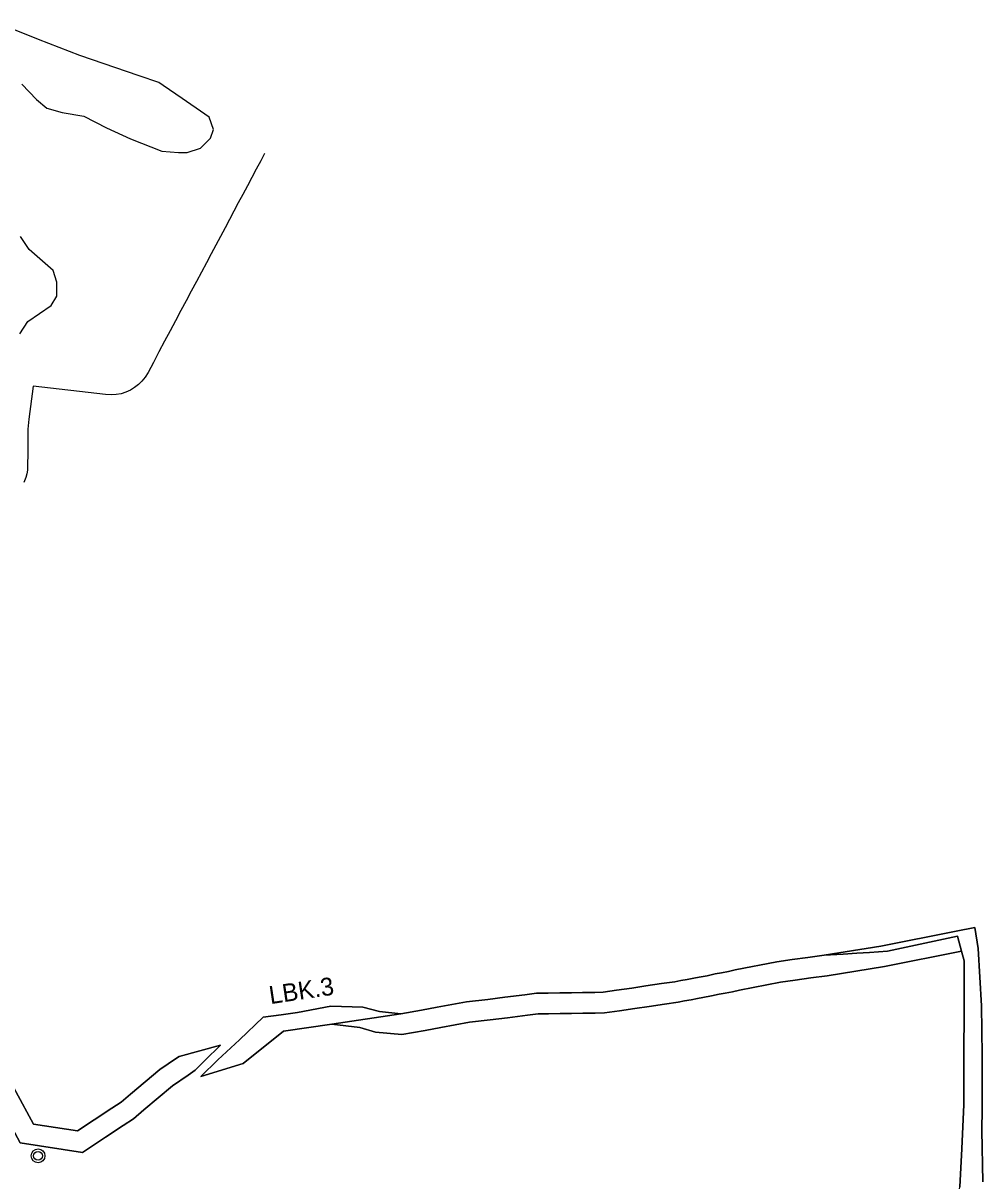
# Model space of a CAD drawing. Extents: x -555426 to -553015, y -1186745 to -1182595.
# Drawn here: x -554236 to -553538, y -1183544 to -1182702 of the extents above; entities that cross this region are included whole.
import ezdxf

# ---------------------------------------------------------------- set-up
doc = ezdxf.new("R2010")
doc.units = 0
for name, color, linetype in [('Level 12', 7, 'Continuous'), ('Level 50', 7, 'Continuous'), ('Level 7', 7, 'Continuous'), ('svahove_deformace', 7, 'Continuous'), ('USES_ID', 7, 'Continuous'), ('USES_LBK_navrh', 7, 'Continuous'), ('USES_LBK_stav', 7, 'Continuous')]:
    doc.layers.add(name, color=color, linetype=linetype)

msp = doc.modelspace()

# ---------------------------------------------------------------- linework, layer by layer
at = {"layer": 'Level 12'}
for points in [[(-554110.58, -1183463.31), (-554103.48, -1183456.27), (-554092.27, -1183445.06), (-554122.23, -1183453.2), (-554124.21, -1183454.61), (-554136.18, -1183462.63), (-554157.58, -1183480.55), (-554164.41, -1183486.48), (-554171.22, -1183490.93), (-554184.03, -1183499.31), (-554196.04, -1183507.39), (-554228.05, -1183502.41), (-554240.95, -1183478.72), (-554274.26, -1183417.7), (-554310.48, -1183350.45), (-554361.08, -1183256.6), (-554365.04, -1183259.86)], [(-554365.04, -1183259.86), (-554366.04, -1183279.01), (-554323.69, -1183357.57), (-554287.45, -1183424.85), (-554254.12, -1183485.9), (-554237.68, -1183516.1), (-554192.54, -1183523.12), (-554175.73, -1183511.81), (-554163.01, -1183503.48), (-554155.35, -1183498.48), (-554147.85, -1183491.97), (-554127.17, -1183474.65), (-554115.67, -1183466.95), (-554110.58, -1183463.31)], [(-553538.15, -1183544.35), (-553538.85, -1183507), (-553538.59, -1183491.21), (-553538.57, -1183472.91), (-553538.64, -1183452.23), (-553539.18, -1183416.53), (-553541.45, -1183374.79), (-553543.94, -1183359.47), (-553557.65, -1183362.2), (-553612.39, -1183373.1), (-553653.56, -1183379.74), (-553665.24, -1183381.36), (-553676.67, -1183382.9), (-553687.79, -1183384.46), (-553718.16, -1183390.43), (-553722.99, -1183391.53), (-553728.14, -1183392.45), (-553732.81, -1183393.34), (-553738.51, -1183394.57), (-553744.23, -1183395.71), (-553748.21, -1183396.36), (-553752.95, -1183397.28), (-553757.56, -1183398.09), (-553762.06, -1183398.94), (-553771.65, -1183400.34), (-553782.96, -1183402.01), (-553793.28, -1183403.54), (-553804.29, -1183405.2), (-553814.16, -1183406.62), (-553820.26, -1183406.69), (-553829.02, -1183406.87), (-553837.21, -1183407), (-553845.49, -1183407.06), (-553853.98, -1183407.2), (-553862.46, -1183407.33), (-553870.96, -1183408.4), (-553885.46, -1183410.23), (-553897.94, -1183411.82), (-553913.31, -1183413.52), (-553934.77, -1183417.42), (-553946.22, -1183419.56), (-553961.04, -1183422.25), (-553976.68, -1183420.7), (-553988.73, -1183417.33), (-554011.96, -1183416.74), (-554036.25, -1183421.25), (-554048.21, -1183422.95), (-554061.25, -1183424.79), (-554078.44, -1183441.14), (-554094.02, -1183455.82), (-554106.58, -1183467.73)], [(-554106.58, -1183467.73), (-554075.73, -1183458.42), (-554046.43, -1183434.94), (-554011.18, -1183429.7), (-553990.97, -1183432.28), (-553979.46, -1183435.5), (-553960.43, -1183437.38), (-553943.5, -1183434.31), (-553932.05, -1183432.17), (-553911.14, -1183428.37), (-553896.17, -1183426.72), (-553883.57, -1183425.11), (-553869.08, -1183423.28), (-553861.41, -1183422.32), (-553853.74, -1183422.2), (-553845.31, -1183422.06), (-553837.04, -1183422), (-553828.75, -1183421.87), (-553820.02, -1183421.69), (-553813, -1183421.61), (-553802.1, -1183420.04), (-553791.06, -1183418.38), (-553780.77, -1183416.85), (-553769.47, -1183415.18), (-553759.58, -1183413.74), (-553754.87, -1183412.85), (-553750.22, -1183412.03), (-553745.57, -1183411.13), (-553741.55, -1183410.47), (-553735.46, -1183409.26), (-553729.82, -1183408.04), (-553725.42, -1183407.2), (-553720, -1183406.23), (-553715.05, -1183405.1), (-553685.3, -1183399.26), (-553674.63, -1183397.76), (-553663.21, -1183396.22), (-553651.33, -1183394.57), (-553609.73, -1183387.86), (-553553.6, -1183376.69), (-553551.63, -1183383.72), (-553552.01, -1183488.29), (-553553.42, -1183520.28), (-553554.96, -1183548.08)]]:
    msp.add_lwpolyline(points, dxfattribs=at)
at = {"layer": 'Level 50'}
for radius in [5, 3.23]:
    msp.add_circle((-554224.81, -1183525.49), radius, dxfattribs=at)
at = {"layer": 'Level 7'}
msp.add_lwpolyline([(-554060.18, -1182797.13), (-554062.96, -1182802.34), (-554066.26, -1182808.55), (-554069.5, -1182814.65), (-554072.68, -1182820.62), (-554076.02, -1182826.88), (-554079.3, -1182833.05), (-554088.9, -1182851.04), (-554092.27, -1182857.39), (-554095.64, -1182863.71), (-554099, -1182870), (-554102.44, -1182876.46), (-554106.07, -1182883.28), (-554109.75, -1182890.2), (-554113.47, -1182897.16), (-554117.18, -1182904.12), (-554120.9, -1182911.12), (-554124.95, -1182918.73), (-554128.86, -1182926.05), (-554132.82, -1182933.49), (-554136.92, -1182941.19), (-554141, -1182948.85), (-554144.88, -1182956.13), (-554147.06, -1182959.69), (-554149.28, -1182962.5), (-554151.82, -1182965.02), (-554154.64, -1182967.22), (-554157.71, -1182969.07), (-554160.97, -1182970.55), (-554164.39, -1182971.62), (-554167.91, -1182972.27), (-554171.48, -1182972.5), (-554175.65, -1182972.28), (-554228.45, -1182966.21), (-554231.49, -1182990.1), (-554232.22, -1182997.37), (-554232.21, -1183005.27), (-554232.33, -1183014.86), (-554232.38, -1183023.78), (-554232.55, -1183027.13), (-554232.98, -1183029.87), (-554233.69, -1183032.56), (-554235.05, -1183036.12)], dxfattribs=at)
at = {"layer": 'svahove_deformace'}
for p, q in [((-554224.4, -1182714.16), (-554254.15, -1182702.37)), ((-554194.54, -1182725.99), (-554224.4, -1182714.16)), ((-554133.74, -1182747.74), (-554136.89, -1182745.57))]:
    msp.add_line(p, q, dxfattribs=at)
for points in [[(-554136.89, -1182745.57), (-554151.25, -1182740.69), (-554194.54, -1182725.99)], [(-554236.48, -1182746.72), (-554225.9, -1182757.83), (-554218.49, -1182764.18), (-554207.38, -1182767.36), (-554191.5, -1182770), (-554175.1, -1182778.47), (-554157.64, -1182786.41), (-554134.88, -1182795.4), (-554122.71, -1182796.46), (-554116.36, -1182796.46), (-554106.84, -1182793.29), (-554099.43, -1182785.88), (-554097.31, -1182779.53), (-554100.41, -1182770.76)], [(-554100.41, -1182770.76), (-554100.41, -1182770.76), (-554103.65, -1182768.52), (-554120.11, -1182757.15), (-554133.74, -1182747.74)], [(-554238.07, -1182928.22), (-554232.25, -1182919.23), (-554215.32, -1182907.59), (-554211.08, -1182900.71), (-554211.08, -1182890.65), (-554213.73, -1182882.19), (-554231.19, -1182866.84), (-554237.54, -1182857.31)]]:
    msp.add_lwpolyline(points, dxfattribs=at)
at = {"layer": 'USES_LBK_navrh'}
for p, q in [((-553607.36, -1183376.83), (-553556.6, -1183365.96)), ((-553556.6, -1183365.96), (-553553.6, -1183376.69)), ((-553687.79, -1183384.46), (-553676.67, -1183382.9)), ((-553676.67, -1183382.9), (-553665.24, -1183381.36)), ((-553665.24, -1183381.36), (-553653.56, -1183379.74)), ((-553653.56, -1183379.74), (-553639.56, -1183378.81)), ((-553639.56, -1183378.81), (-553629.85, -1183378.3)), ((-553629.85, -1183378.3), (-553620.62, -1183377.81)), ((-553620.62, -1183377.81), (-553607.36, -1183376.83)), ((-553732.81, -1183393.34), (-553728.14, -1183392.45)), ((-553728.14, -1183392.45), (-553722.99, -1183391.53)), ((-553752.95, -1183397.28), (-553748.21, -1183396.36)), ((-553748.21, -1183396.36), (-553744.23, -1183395.71)), ((-553744.23, -1183395.71), (-553738.51, -1183394.57)), ((-553738.51, -1183394.57), (-553732.81, -1183393.34)), ((-553685.3, -1183399.26), (-553715.05, -1183405.1)), ((-553651.33, -1183394.57), (-553663.21, -1183396.22)), ((-553885.46, -1183410.23), (-553870.96, -1183408.4)), ((-553870.96, -1183408.4), (-553862.46, -1183407.33)), ((-553862.46, -1183407.33), (-553853.98, -1183407.2)), ((-553853.98, -1183407.2), (-553845.49, -1183407.06)), ((-553829.02, -1183406.87), (-553820.26, -1183406.69)), ((-553820.26, -1183406.69), (-553814.16, -1183406.62)), ((-553715.05, -1183405.1), (-553720, -1183406.23)), ((-553913.31, -1183413.52), (-553897.94, -1183411.82)), ((-553897.94, -1183411.82), (-553885.46, -1183410.23)), ((-554011.18, -1183429.7), (-553961.04, -1183422.25)), ((-553961.04, -1183422.25), (-553946.22, -1183419.56)), ((-553853.74, -1183422.2), (-553861.41, -1183422.32)), ((-553845.31, -1183422.06), (-553853.74, -1183422.2)), ((-553990.97, -1183432.28), (-554011.18, -1183429.7)), ((-553943.5, -1183434.31), (-553960.43, -1183437.38)), ((-553932.05, -1183432.17), (-553943.5, -1183434.31)), ((-553911.14, -1183428.37), (-553932.05, -1183432.17)), ((-554122.23, -1183453.2), (-554092.27, -1183445.06)), ((-554092.27, -1183445.06), (-554103.48, -1183456.27)), ((-554103.48, -1183456.27), (-554110.58, -1183463.31)), ((-554115.67, -1183466.95), (-554127.17, -1183474.65)), ((-554110.58, -1183463.31), (-554115.67, -1183466.95)), ((-554127.17, -1183474.65), (-554147.85, -1183491.97)), ((-554184.03, -1183499.31), (-554171.22, -1183490.93)), ((-554147.85, -1183491.97), (-554155.35, -1183498.48)), ((-554155.35, -1183498.48), (-554163.01, -1183503.48)), ((-554163.01, -1183503.48), (-554175.73, -1183511.81))]:
    msp.add_line(p, q, dxfattribs=at)
for points in [[(-554310.48, -1183350.45), (-554274.26, -1183417.7), (-554240.95, -1183478.72), (-554228.05, -1183502.41), (-554196.04, -1183507.39), (-554184.03, -1183499.31)], [(-553722.99, -1183391.53), (-553718.16, -1183390.43), (-553687.79, -1183384.46)], [(-553553.6, -1183376.69), (-553609.73, -1183387.86), (-553651.33, -1183394.57)], [(-553814.16, -1183406.62), (-553804.29, -1183405.2), (-553793.28, -1183403.54), (-553782.96, -1183402.01), (-553771.65, -1183400.34), (-553762.06, -1183398.94), (-553757.56, -1183398.09), (-553752.95, -1183397.28)], [(-553663.21, -1183396.22), (-553674.63, -1183397.76), (-553685.3, -1183399.26)], [(-553845.49, -1183407.06), (-553837.21, -1183407), (-553829.02, -1183406.87)], [(-553729.82, -1183408.04), (-553735.46, -1183409.26), (-553741.55, -1183410.47), (-553745.57, -1183411.13), (-553750.22, -1183412.03)], [(-553720, -1183406.23), (-553725.42, -1183407.2), (-553729.82, -1183408.04)], [(-553946.22, -1183419.56), (-553934.77, -1183417.42), (-553913.31, -1183413.52)], [(-553750.22, -1183412.03), (-553754.87, -1183412.85), (-553759.58, -1183413.74), (-553769.47, -1183415.18), (-553780.77, -1183416.85), (-553791.06, -1183418.38), (-553802.1, -1183420.04), (-553813, -1183421.61), (-553820.02, -1183421.69), (-553828.75, -1183421.87), (-553837.04, -1183422), (-553845.31, -1183422.06)], [(-553883.57, -1183425.11), (-553896.17, -1183426.72), (-553911.14, -1183428.37)], [(-553861.41, -1183422.32), (-553869.08, -1183423.28), (-553883.57, -1183425.11)], [(-553960.43, -1183437.38), (-553979.46, -1183435.5), (-553990.97, -1183432.28)], [(-554157.58, -1183480.55), (-554136.18, -1183462.63), (-554124.21, -1183454.61), (-554122.23, -1183453.2)], [(-554171.22, -1183490.93), (-554164.41, -1183486.48), (-554157.58, -1183480.55)], [(-554175.73, -1183511.81), (-554192.54, -1183523.12), (-554237.68, -1183516.1), (-554254.12, -1183485.9)]]:
    msp.add_lwpolyline(points, dxfattribs=at)
at = {"layer": 'USES_LBK_stav'}
for p, q in [((-553556.6, -1183365.96), (-553607.36, -1183376.83)), ((-553553.6, -1183376.69), (-553556.6, -1183365.96)), ((-553639.56, -1183378.81), (-553653.56, -1183379.74)), ((-553629.85, -1183378.3), (-553639.56, -1183378.81)), ((-553620.62, -1183377.81), (-553629.85, -1183378.3)), ((-553607.36, -1183376.83), (-553620.62, -1183377.81)), ((-553961.04, -1183422.25), (-554011.18, -1183429.7))]:
    msp.add_line(p, q, dxfattribs=at)
for points in [[(-553653.56, -1183379.74), (-553612.39, -1183373.1), (-553557.65, -1183362.2), (-553543.94, -1183359.47), (-553541.45, -1183374.79), (-553539.18, -1183416.53), (-553538.64, -1183452.23), (-553538.57, -1183472.91), (-553538.59, -1183491.21), (-553538.85, -1183507), (-553538.15, -1183544.35)], [(-553666.31, -1183877.64), (-553659.67, -1183865.22), (-553655.99, -1183866.78), (-553650.17, -1183865.76), (-553638.05, -1183859.17), (-553599.33, -1183779.63), (-553598.72, -1183776.49), (-553583.88, -1183732.87), (-553570.03, -1183665.12), (-553560.51, -1183589.02), (-553554.96, -1183548.08), (-553553.42, -1183520.28), (-553552.01, -1183488.29), (-553551.63, -1183383.72), (-553553.6, -1183376.69)], [(-554106.58, -1183467.73), (-554094.02, -1183455.82), (-554078.44, -1183441.14), (-554061.25, -1183424.79), (-554048.21, -1183422.95), (-554036.25, -1183421.25), (-554011.96, -1183416.74), (-553988.73, -1183417.33), (-553976.68, -1183420.7), (-553961.04, -1183422.25)], [(-554011.18, -1183429.7), (-554046.43, -1183434.94), (-554075.73, -1183458.42), (-554106.58, -1183467.73)]]:
    msp.add_lwpolyline(points, dxfattribs=at)

# ---------------------------------------------------------------- texts
at = {"layer": 'USES_ID'}
msp.add_text('LBK.3', height=13, rotation=8.53964, dxfattribs=at).set_placement((-554055.89, -1183415.28))

doc.saveas('drawing.dxf')
